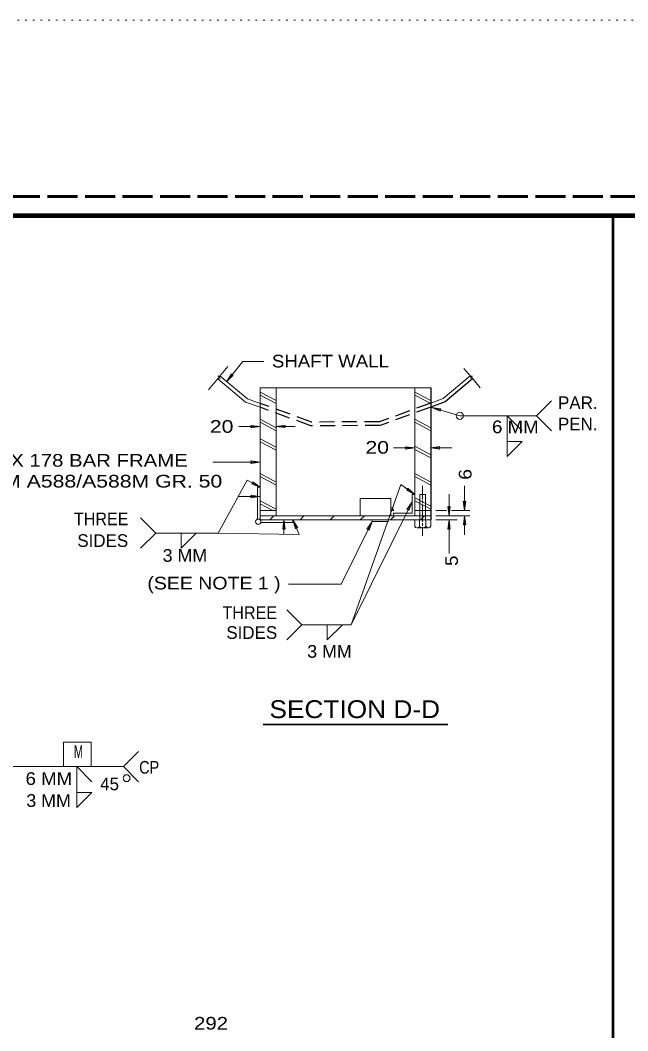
# Model space of a CAD drawing. Extents: x 312583 to 312854, y 144419 to 144597.
# Drawn here: x 312762.8 to 312799.2, y 144536.2 to 144596.8 of the extents above; entities that cross this region are included whole.
import ezdxf
from ezdxf.enums import TextEntityAlignment as Align

# ---------------------------------------------------------------- set-up
doc = ezdxf.new("R2010")
doc.units = 0
doc.header["$LTSCALE"] = 0.3
for name, pattern in [('DOTTED', [1.5, 0.3, -1.2]), ('LONG_DASHED', [7.5, 6, -1.5]), ('MEDIUM_DASHED', [4.5, 3, -1.5])]:
    doc.linetypes.add(name, pattern=pattern)
for name, color, linetype, lineweight in [('1', 7, 'Continuous', 13), ('2', 7, 'Continuous', 13), ('61', 7, 'LONG_DASHED', 60), ('63', 7, 'DOTTED', 13)]:
    doc.layers.add(name, color=color, linetype=linetype, lineweight=lineweight)

msp = doc.modelspace()

# ---------------------------------------------------------------- linework, layer by layer
at = {"layer": '1', "lineweight": 53}
msp.add_line((312798.3536, 144585.0846), (312798.3536, 144491.5236), dxfattribs=at)
at = {"layer": '1'}
for p, q in [((312778.1584, 144573.9846), (312777.2001, 144574.4906)), ((312787.4274, 144573.9846), (312786.4691, 144574.4906)), ((312778.1584, 144573.8006), (312777.2001, 144574.3143)), ((312787.4274, 144573.8006), (312786.4691, 144574.3143)), ((312793.7754, 144573.0723), (312794.6724, 144573.977)), ((312789.1677, 144573.0723), (312787.4887, 144573.5706)), ((312778.1584, 144572.3516), (312777.2001, 144572.8653)), ((312778.1584, 144572.1753), (312777.2001, 144572.6813)), ((312787.4274, 144572.3516), (312786.4691, 144572.8653)), ((312787.4274, 144572.1753), (312786.4691, 144572.6813)), ((312792.0044, 144573.0723), (312792.0044, 144571.5313)), ((312792.0044, 144573.0723), (312792.9091, 144572.1676)), ((312793.7754, 144573.0723), (312794.6724, 144572.1676)), ((312778.1584, 144571.1863), (312777.2001, 144571.6923)), ((312778.1584, 144571.0023), (312777.2001, 144571.516)), ((312792.0044, 144570.6266), (312792.9091, 144571.5313)), ((312792.0044, 144571.5313), (312792.0044, 144570.6266)), ((312792.9091, 144571.5313), (312792.0044, 144571.5313)), ((312787.4274, 144570.7263), (312786.4691, 144571.24)), ((312787.4274, 144570.5423), (312786.4691, 144571.056)), ((312778.1584, 144569.101), (312777.2001, 144569.607)), ((312787.4274, 144569.101), (312786.4691, 144569.607)), ((312778.1584, 144568.917), (312777.2001, 144569.4306)), ((312787.4274, 144568.917), (312786.4691, 144569.4306)), ((312782.6587, 144560.5296), (312785.6334, 144568.9476)), ((312786.4691, 144568.3496), (312785.6334, 144568.9476)), ((312778.1584, 144567.468), (312777.2001, 144567.9816)), ((312777.9591, 144567.3913), (312777.2001, 144567.7976)), ((312782.6587, 144560.5296), (312786.3081, 144567.9126)), ((312787.4274, 144567.652), (312786.4691, 144568.158)), ((312787.4274, 144567.468), (312786.4691, 144567.9816)), ((312770.0317, 144566.9466), (312770.9364, 144566.042)), ((312777.7827, 144566.8316), (312778.0281, 144567.077)), ((312779.5921, 144566.8316), (312779.8297, 144567.077)), ((312781.4014, 144566.8316), (312781.6391, 144567.077)), ((312782.0607, 144562.983), (312783.9084, 144566.732)), ((312783.2031, 144566.8316), (312783.4484, 144567.077)), ((312785.0124, 144566.8316), (312785.2501, 144567.077)), ((312786.8217, 144566.8316), (312787.0594, 144567.077)), ((312770.0317, 144565.1373), (312770.9364, 144566.042)), ((312772.4621, 144565.1373), (312773.3667, 144566.042)), ((312772.4621, 144566.042), (312772.4621, 144565.1373)), ((312778.8944, 144562.983), (312782.0607, 144562.983)), ((312778.7947, 144561.4343), (312779.6994, 144560.5296)), ((312778.7947, 144559.6326), (312779.6994, 144560.5296)), ((312779.6994, 144560.5296), (312782.6587, 144560.5296)), ((312781.2251, 144559.6326), (312782.1297, 144560.5296)), ((312781.2251, 144560.5296), (312781.2251, 144559.6326)), ((312765.4127, 144553.5052), (312765.4127, 144552.0409)), ((312765.4127, 144553.5052), (312767.0764, 144553.5052)), ((312767.0764, 144552.0409), (312767.0764, 144553.5052)), ((312769.0007, 144552.0409), (312769.9054, 144552.9379)), ((312766.2024, 144552.0409), (312766.2024, 144550.4922)), ((312766.2024, 144552.0409), (312767.107, 144551.1362)), ((312769.0007, 144552.0409), (312769.9054, 144551.1362)), ((312766.2024, 144549.5952), (312767.107, 144550.4922)), ((312766.2024, 144550.4922), (312766.2024, 144549.5952)), ((312767.107, 144550.4922), (312766.2024, 144550.4922))]:
    msp.add_line(p, q, dxfattribs=at)
at = {"layer": '1', "lineweight": 35}
msp.add_line((312777.3819, 144554.5573), (312788.4519, 144554.5573), dxfattribs=at)
at = {"layer": '1', "lineweight": 158}
msp.add_lwpolyline([(312616.5, 144423.1446), (312616.5, 144585.0846), (312849, 144585.0846)], dxfattribs=at)
at = {"layer": '1'}
for points in [[(312775.5824, 144575.5026), (312775.1837, 144575.1116), (312775.4751, 144575.5946), (312775.4981, 144575.5026)], [(312788.0024, 144573.3483), (312787.4887, 144573.5706), (312788.0407, 144573.4863), (312787.9717, 144573.425)], [(312776.6481, 144572.4973), (312777.2001, 144572.4283), (312776.6481, 144572.3516), (312776.7017, 144572.4283)], [(312778.7104, 144572.3593), (312778.1584, 144572.4283), (312778.7104, 144572.505), (312778.6567, 144572.4283)], [(312785.9171, 144571.217), (312786.4691, 144571.148), (312785.9171, 144571.0713), (312785.9707, 144571.148)], [(312787.9794, 144571.079), (312787.4274, 144571.148), (312787.9794, 144571.2246), (312787.9257, 144571.148)], [(312776.6481, 144570.366), (312777.2001, 144570.297), (312776.6481, 144570.2203), (312776.7017, 144570.297)], [(312776.7554, 144569.1163), (312777.2001, 144568.7943), (312776.6787, 144568.9936), (312776.7631, 144569.032)], [(312786.0551, 144568.7253), (312786.4691, 144568.3496), (312785.9707, 144568.6103), (312786.0551, 144568.641)], [(312776.6481, 144568.3036), (312777.2001, 144568.2346), (312776.6481, 144568.158), (312776.7017, 144568.2346)], [(312785.9937, 144567.4526), (312786.3081, 144567.9126), (312786.1241, 144567.3836), (312786.0857, 144567.468)], [(312789.5281, 144567.9433), (312789.4591, 144567.3913), (312789.3824, 144567.9433), (312789.4591, 144567.8896)], [(312788.5927, 144567.629), (312788.5237, 144567.077), (312788.4471, 144567.629), (312788.5237, 144567.5753)], [(312778.5571, 144566.2796), (312778.6261, 144566.8316), (312778.7027, 144566.2796), (312778.6261, 144566.3333)], [(312779.3161, 144566.3026), (312779.1551, 144566.8316), (312779.4541, 144566.3563), (312779.3621, 144566.3793)], [(312783.6017, 144566.272), (312783.9084, 144566.732), (312783.7321, 144566.2106), (312783.6861, 144566.2873)], [(312788.4547, 144566.2796), (312788.5237, 144566.8316), (312788.6004, 144566.2796), (312788.5237, 144566.3333)], [(312788.4547, 144566.2796), (312788.5237, 144566.8316), (312788.6004, 144566.2796), (312788.5237, 144566.3333)], [(312789.3901, 144566.525), (312789.4591, 144567.077), (312789.5357, 144566.525), (312789.4591, 144566.5786)]]:
    msp.add_lwpolyline(points, close=True, dxfattribs=at)
msp.add_circle((312769.1892, 144551.3464), 0.2074, dxfattribs=at)
at = {"layer": '2'}
for p, q in [((312775.1837, 144575.1116), (312776.1574, 144576.3153)), ((312776.1574, 144576.3153), (312777.4301, 144576.3153)), ((312775.2604, 144576.0163), (312774.7621, 144575.426)), ((312789.4207, 144575.909), (312789.8271, 144575.426)), ((312774.1027, 144574.6363), (312774.7007, 144575.3493)), ((312790.3944, 144574.7513), (312789.9037, 144575.3416)), ((312777.2001, 144574.7436), (312787.4274, 144574.7436)), ((312777.2001, 144566.8316), (312777.2001, 144574.7436)), ((312778.1584, 144567.3913), (312778.1584, 144574.7436)), ((312786.4691, 144574.7436), (312786.4691, 144567.3913)), ((312789.1677, 144573.0723), (312793.7754, 144573.0723)), ((312777.2001, 144572.4283), (312775.9274, 144572.4283)), ((312778.1584, 144572.4283), (312779.3007, 144572.4283)), ((312786.4691, 144571.148), (312785.1887, 144571.148)), ((312787.4274, 144571.148), (312788.7001, 144571.148)), ((312774.3557, 144570.297), (312777.2001, 144570.297)), ((312776.4257, 144569.216), (312774.6854, 144566.042)), ((312777.2001, 144568.7943), (312776.4257, 144569.216)), ((312777.0391, 144566.8776), (312777.0391, 144568.7943)), ((312777.0391, 144568.7943), (312777.2001, 144568.7943)), ((312786.9444, 144568.871), (312786.9444, 144568.066)), ((312789.4591, 144567.3913), (312789.4591, 144568.871)), ((312777.2001, 144568.2346), (312775.8891, 144568.2346)), ((312783.1954, 144567.077), (312783.1954, 144568.112)), ((312786.7834, 144566.8316), (312786.7834, 144568.3496)), ((312786.7834, 144568.3496), (312787.1054, 144568.3496)), ((312786.9444, 144567.8283), (312786.9444, 144567.9893)), ((312787.1054, 144568.3496), (312787.1054, 144566.8316)), ((312788.5237, 144567.077), (312788.5237, 144568.365)), ((312777.2001, 144567.3913), (312778.1584, 144567.3913)), ((312785.0277, 144567.5523), (312785.1121, 144567.5523)), ((312785.0277, 144567.3913), (312785.1887, 144567.3913)), ((312786.3081, 144567.2303), (312785.1887, 144567.2303)), ((312785.1887, 144567.2303), (312785.1887, 144567.077)), ((312787.4274, 144567.3913), (312786.4691, 144567.3913)), ((312786.9444, 144567.7516), (312786.9444, 144566.709)), ((312787.7417, 144567.3913), (312788.3704, 144567.3913)), ((312789.7811, 144567.3913), (312788.6694, 144567.3913)), ((312787.4274, 144567.077), (312777.2001, 144567.077)), ((312787.4274, 144566.8316), (312777.2001, 144566.8316)), ((312777.2384, 144566.6706), (312779.1551, 144566.6706)), ((312778.6261, 144566.8316), (312778.6261, 144565.973)), ((312779.1551, 144566.6706), (312779.1551, 144566.8316)), ((312779.1551, 144566.8316), (312779.5461, 144565.95)), ((312784.8667, 144566.732), (312784.8667, 144566.8316)), ((312786.4691, 144566.433), (312786.4691, 144566.8316)), ((312786.7451, 144566.433), (312786.7451, 144566.8316)), ((312786.9444, 144566.6323), (312786.9444, 144566.4713)), ((312787.1437, 144566.8316), (312787.1437, 144566.433)), ((312787.4274, 144566.8316), (312787.4274, 144566.433)), ((312787.7417, 144567.077), (312789.7811, 144567.077)), ((312787.7417, 144566.8316), (312789.0067, 144566.8316)), ((312788.5237, 144564.8192), (312788.5237, 144566.8316)), ((312789.4591, 144565.9423), (312789.4591, 144567.077)), ((312774.6854, 144566.042), (312770.9364, 144566.042)), ((312774.6854, 144566.042), (312779.5461, 144565.95)), ((312787.2817, 144566.3563), (312786.6071, 144566.3563)), ((312786.9444, 144565.8656), (312786.9444, 144566.3946))]:
    msp.add_line(p, q, dxfattribs=at)
at = {"layer": '2', "lineweight": 25}
msp.add_line((312787.4274, 144574.7436), (312787.4274, 144566.8316), dxfattribs=at)
at = {"layer": '2'}
for points in [[(312774.6547, 144575.2956), (312776.3261, 144573.8926), (312777.2001, 144573.5783)], [(312774.7621, 144575.426), (312774.6854, 144575.4566), (312774.8004, 144575.311), (312774.7007, 144575.3493)], [(312774.7927, 144575.4643), (312776.4411, 144574.0843), (312777.2001, 144573.816)], [(312789.7964, 144575.4643), (312788.1787, 144574.0996), (312787.4274, 144573.8313)], [(312789.8271, 144575.426), (312789.9114, 144575.4566), (312789.8041, 144575.3186), (312789.9037, 144575.3416)], [(312785.0277, 144567.077), (312785.0277, 144568.112), (312783.1954, 144568.112)], [(312786.3081, 144567.2303), (312786.3081, 144568.3496), (312786.4691, 144568.3496)], [(312785.1887, 144567.3913), (312785.1887, 144567.4296), (312785.1121, 144567.5523)], [(312784.8667, 144566.732), (312783.9084, 144566.732), (312783.9084, 144566.8316)], [(312753.629, 144546.4519), (312756.9104, 144552.0409), (312769.0007, 144552.0409)]]:
    msp.add_lwpolyline(points, dxfattribs=at)
at = {"layer": '2', "lineweight": 25}
msp.add_lwpolyline([(312789.9421, 144575.2956), (312788.2937, 144573.908), (312787.4274, 144573.5936)], dxfattribs=at)
at = {"layer": '2', "linetype": 'MEDIUM_DASHED', "lineweight": 25}
for points in [[(312787.4274, 144573.8313), (312784.3531, 144572.7043), (312780.2744, 144572.6966), (312777.2001, 144573.816)], [(312787.4274, 144573.5936), (312784.3914, 144572.482), (312780.2361, 144572.4743), (312777.2001, 144573.5783)]]:
    msp.add_lwpolyline(points, dxfattribs=at)
at = {"layer": '2'}
for points in [[(312778.1584, 144567.3913), (312777.2001, 144567.3913), (312777.2001, 144567.077), (312778.1584, 144567.077)], [(312786.4691, 144567.3913), (312787.4274, 144567.3913), (312787.4274, 144567.077), (312786.4691, 144567.077)]]:
    msp.add_lwpolyline(points, close=True, dxfattribs=at)
for centre, radius in [((312789.1696, 144573.0723), 0.2145), ((312777.0882, 144566.7217), 0.1597)]:
    msp.add_circle(centre, radius, dxfattribs=at)
for centre, radius, start, end in [((312786.6052, 144566.5182), 0.1632, 210.96127, 329.03872), ((312786.9457, 144566.6487), 0.2937, 226.90941, 312.72449), ((312787.2839, 144566.5177), 0.1627, 211.39847, 329.12718)]:
    msp.add_arc(centre, radius, start, end, dxfattribs=at)
at = {"layer": '61'}
msp.add_line((312851.75, 144586.2246), (312583.526, 144586.2246), dxfattribs=at)
at = {"layer": '63'}
msp.add_line((312601.2, 144596.7846), (312853.5, 144596.7846), dxfattribs=at)

# ---------------------------------------------------------------- texts
at = {"layer": '1'}
for s, width, p in [('SHAFT WALL', 1.1, (312777.9035, 144575.9674)), ('20 ', 1.25, (312774.185, 144572.0497)), ('6 MM', 1.1, (312791.1027, 144572.0267)), ('20 ', 1.25, (312783.5122, 144570.7989)), ('M20 X 178 BAR FRAME', 1.2, (312759.5073, 144570.0193)), ('ASTM A588/A588M GR. 50', 1.25, (312759.3227, 144568.7696)), ('THREE', 0.95, (312766.0327, 144566.5125)), ('3 MM', 1.05, (312771.3557, 144564.3194)), ('(SEE NOTE 1 )', 1.15, (312770.4383, 144562.6604)), ('THREE', 0.95, (312774.9424, 144560.8895)), ('3 MM', 1.05, (312780.0235, 144558.5659)), ('M', 0.65, (312766.0313, 144552.5633)), ('CP', 0.85, (312769.9472, 144551.6169)), ('6 MM', 1.1, (312763.1342, 144550.9392)), ('3 MM', 1.05, (312763.1802, 144549.6264)), ('292 ', 1.2, (312773.2381, 144536.2725))]:
    msp.add_text(s, height=0.76, dxfattribs=dict(at, width=width)).set_placement(p)
for s, p in [('PAR.', (312795.0624, 144573.4705)), ('PEN.', (312795.0546, 144572.1924)), ('SIDES', (312766.2398, 144565.2092)), ('SIDES', (312775.1724, 144559.6958)), ('45', (312767.607, 144550.6214))]:
    msp.add_text(s, height=0.76, dxfattribs=at).set_placement(p)
for s, width, p in [('6 ', 1.15, (312789.8745, 144569.2334)), ('5 ', 1.1, (312789.0541, 144564.0688))]:
    msp.add_text(s, height=0.76, rotation=90, dxfattribs=dict(at, width=width)).set_placement(p)
at = {"layer": '1', "width": 1.1}
msp.add_text('SECTION D-D', height=1.07, dxfattribs=at).set_placement((312782.8714, 144554.9476), align=Align.CENTER)

doc.saveas('drawing.dxf')
